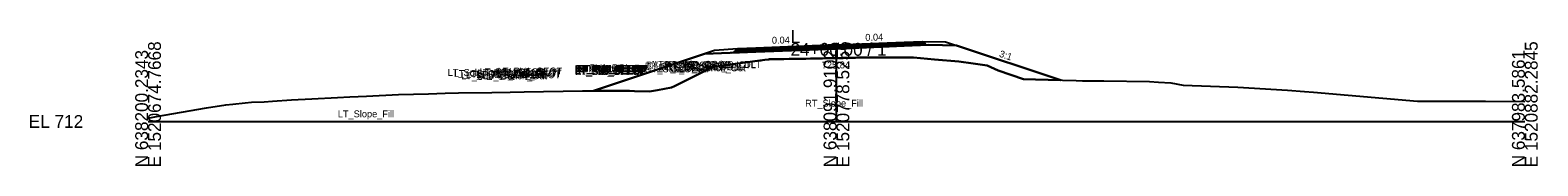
# Model space of a CAD drawing. Extents: x -26 to 3903, y -10 to 9531.
# Drawn here: x 974.3 to 1302.8, y 3990.3 to 4019.9 of the extents above; entities that cross this region are included whole.
import ezdxf

# ---------------------------------------------------------------- set-up
doc = ezdxf.new("R2010")
doc.units = 0
for name, color, linetype in [('Default', 7, 'Continuous'), ('Exist Cross Section Cell', 7, 'Continuous'), ('Exist XS Center Line Elevation Label', 7, 'Continuous'), ('Exist XS Ground Line', 7, 'Continuous'), ('Prop CMT Conc Surface', 7, 'Continuous'), ('Prop CMT Pvmt Course 1', 7, 'Continuous'), ('Prop CMT Pvmt Course 2', 7, 'Continuous'), ('Prop CMT Pvmt Course 3', 7, 'Continuous'), ('Prop CMT Pvmt Surface', 7, 'Continuous'), ('Prop CMT Pvmt Surface Shoulder', 7, 'Continuous'), ('Prop CMT Shld Paved Course 1', 7, 'Continuous'), ('Prop CMT Shld Paved Course 2', 7, 'Continuous'), ('Prop CMT Shld Paved Course 3', 7, 'Continuous'), ('Prop CMT Slope Grass', 7, 'Continuous'), ('Prop CMT Subgrade Earthwork', 7, 'Continuous'), ('Prop XS Earthwork Shape', 7, 'Continuous'), ('Prop XS SE Text', 7, 'Continuous'), ('Prop XS Side Slope Text', 7, 'Continuous')]:
    doc.layers.add(name, color=color, linetype=linetype)

msp = doc.modelspace()

# ---------------------------------------------------------------- linework, layer by layer
at = {"layer": 'Exist Cross Section Cell'}
for p, q in [((1150, 4000), (1150, 4017.14)), ((1000, 4000), (1150, 4000)), ((1150, 4000), (1300, 4000))]:
    msp.add_line(p, q, dxfattribs=at)
at = {"layer": 'Exist XS Ground Line'}
msp.add_lwpolyline([(1000, 4000.71), (1001.87, 4001.06), (1012.72, 4002.98), (1016.94, 4003.62), (1018.49, 4003.79), (1021.17, 4004.04), (1022.57, 4004.18), (1025.3, 4004.32), (1027.1, 4004.46), (1031.28, 4004.75), (1035.65, 4004.93), (1041.25, 4005.2), (1043.99, 4005.38), (1047.58, 4005.5), (1054.57, 4005.86), (1061.09, 4006.03), (1064.71, 4006.18), (1067.62, 4006.24), (1074.94, 4006.31), (1078.92, 4006.39), (1081.98, 4006.48), (1094.64, 4006.67), (1095.14, 4006.67), (1095.79, 4006.67), (1097.45, 4006.67), (1104.89, 4006.67), (1105.99, 4006.63), (1109.27, 4006.55), (1111.03, 4006.83), (1114.04, 4007.38), (1114.68, 4007.71), (1120.53, 4010.62), (1121.55, 4011.11), (1122.79, 4011.84), (1124.76, 4012.16), (1134.42, 4013.45), (1135.21, 4013.56), (1135.27, 4013.56), (1135.4, 4013.57), (1136.27, 4013.59), (1136.63, 4013.59), (1137.45, 4013.61), (1138.57, 4013.62), (1139.72, 4013.64), (1140.33, 4013.65), (1140.93, 4013.66), (1142.12, 4013.68), (1143.35, 4013.7), (1144.37, 4013.72), (1146.94, 4013.78), (1147.4, 4013.79), (1147.83, 4013.8), (1149.3, 4013.83), (1150.07, 4013.85), (1150.15, 4013.85), (1150.44, 4013.85), (1151.3, 4013.87), (1154.17, 4013.92), (1154.46, 4013.93), (1154.74, 4013.93), (1157.77, 4013.98), (1157.99, 4013.99), (1158.2, 4013.99), (1161.38, 4013.99), (1161.66, 4013.99), (1161.83, 4013.99), (1163.85, 4013.99), (1165, 4013.98), (1165.13, 4013.97), (1166.5, 4013.97), (1166.76, 4013.97), (1171.38, 4013.55), (1176.7, 4013.07), (1179.81, 4012.64), (1182.82, 4012.2), (1185.23, 4011.15), (1190.77, 4009.2), (1193.38, 4009.14), (1202.25, 4008.91), (1203.65, 4008.89), (1208.28, 4008.84), (1218.23, 4008.69), (1220.17, 4008.56), (1222.87, 4008.43), (1225.57, 4007.95), (1237.45, 4007.5), (1248.31, 4006.8), (1251.97, 4006.52), (1253.94, 4006.41), (1276.59, 4004.43), (1282.17, 4004.45), (1291.43, 4004.45), (1300, 4004.38)], dxfattribs=at)
at = {"layer": 'Prop CMT Pvmt Course 1'}
for points in [[(1149.97, 4016.73), (1132.41, 4016.02)], [(1132.41, 4015.77), (1149.97, 4016.48)], [(1132.41, 4016.02), (1132.41, 4015.77)], [(1149.97, 4016.73), (1164.76, 4017.32)], [(1164.76, 4017.07), (1149.97, 4016.48)], [(1149.97, 4016.48), (1149.97, 4016.73)], [(1149.97, 4016.48), (1149.97, 4016.73)], [(1164.76, 4017.32), (1164.76, 4017.07)]]:
    msp.add_lwpolyline(points, dxfattribs=at)
msp.add_lwpolyline([(1149.97, 4016.48), (1149.97, 4016.6), (1149.97, 4016.6), (1149.97, 4016.48)], close=True, dxfattribs=at)
msp.add_lwpolyline([(1149.97, 4016.48), (1149.97, 4016.6), (1149.97, 4016.6), (1149.97, 4016.48)], close=True, dxfattribs=at)
at = {"layer": 'Prop CMT Pvmt Course 2'}
for points in [[(1149.97, 4016.48), (1132.41, 4015.77)], [(1132.41, 4015.44), (1149.97, 4016.14)], [(1132.41, 4015.77), (1132.41, 4015.44)], [(1149.97, 4016.48), (1164.76, 4017.07)], [(1164.76, 4016.73), (1149.97, 4016.14)], [(1149.97, 4016.14), (1149.97, 4016.48)], [(1149.97, 4016.14), (1149.97, 4016.48)], [(1164.76, 4017.07), (1164.76, 4016.73)]]:
    msp.add_lwpolyline(points, dxfattribs=at)
at = {"layer": 'Prop CMT Pvmt Course 3'}
for points in [[(1149.97, 4016.14), (1132.41, 4015.44)], [(1132.41, 4015.19), (1149.97, 4015.89)], [(1132.41, 4015.44), (1132.41, 4015.19)], [(1149.97, 4016.14), (1164.76, 4016.73)], [(1164.76, 4016.48), (1149.97, 4015.89)], [(1149.97, 4015.89), (1149.97, 4016.14)], [(1149.97, 4015.89), (1149.97, 4016.14)], [(1164.76, 4016.73), (1164.76, 4016.48)]]:
    msp.add_lwpolyline(points, dxfattribs=at)
at = {"layer": 'Prop CMT Pvmt Surface'}
for points in [[(1149.97, 4016.73), (1132.41, 4016.02)], [(1149.97, 4016.73), (1164.76, 4017.32)]]:
    msp.add_lwpolyline(points, dxfattribs=at)
at = {"layer": 'Prop CMT Pvmt Surface Shoulder'}
for points in [[(1132.41, 4016.02), (1128.41, 4015.86)], [(1164.76, 4017.32), (1168.76, 4017.48)]]:
    msp.add_lwpolyline(points, dxfattribs=at)
at = {"layer": 'Prop CMT Shld Paved Course 1'}
for points in [[(1132.41, 4016.02), (1128.41, 4015.86), (1128.15, 4015.6)], [(1128.15, 4015.6), (1132.41, 4015.77)], [(1132.41, 4015.77), (1132.41, 4016.02)], [(1164.76, 4017.32), (1168.76, 4017.48), (1169, 4017.24)], [(1164.76, 4017.07), (1164.76, 4017.32)], [(1169, 4017.24), (1164.76, 4017.07)]]:
    msp.add_lwpolyline(points, dxfattribs=at)
at = {"layer": 'Prop CMT Shld Paved Course 2'}
for points in [[(1132.41, 4015.77), (1128.15, 4015.6), (1127.8, 4015.26)], [(1127.8, 4015.26), (1132.41, 4015.44)], [(1132.41, 4015.44), (1132.41, 4015.77)], [(1164.76, 4017.07), (1169, 4017.24), (1169.32, 4016.92)], [(1164.76, 4016.73), (1164.76, 4017.07)], [(1169.32, 4016.92), (1164.76, 4016.73)]]:
    msp.add_lwpolyline(points, dxfattribs=at)
at = {"layer": 'Prop CMT Shld Paved Course 3'}
for p, q in [((1127.8, 4015.26), (1127.54, 4014.99)), ((1169.32, 4016.92), (1169.56, 4016.68))]:
    msp.add_line(p, q, dxfattribs=at)
for points in [[(1127.04, 4014.97), (1132.41, 4015.19)], [(1132.41, 4015.44), (1127.8, 4015.26), (1127.54, 4014.99)], [(1132.41, 4015.19), (1132.41, 4015.44)], [(1164.76, 4016.73), (1169.32, 4016.92), (1169.56, 4016.68)], [(1164.76, 4016.48), (1164.76, 4016.73)], [(1170.06, 4016.7), (1164.76, 4016.48)]]:
    msp.add_lwpolyline(points, dxfattribs=at)
at = {"layer": 'Prop CMT Slope Grass'}
for points in [[(1128.41, 4015.86), (1123.41, 4015.46), (1097.03, 4006.67)], [(1168.76, 4017.48), (1173.76, 4017.38), (1198.9, 4009)]]:
    msp.add_lwpolyline(points, dxfattribs=at)
at = {"layer": 'Prop CMT Subgrade Earthwork'}
for points in [[(1132.41, 4015.19), (1121.25, 4014.74)], [(1149.97, 4015.89), (1132.41, 4015.19)], [(1149.97, 4015.89), (1164.76, 4016.48)], [(1164.76, 4016.48), (1170.06, 4016.7)], [(1170.06, 4016.7), (1176.17, 4016.57)]]:
    msp.add_lwpolyline(points, dxfattribs=at)
at = {"layer": 'Prop XS Earthwork Shape'}
for points in [[(1161.83, 4013.99), (1163.85, 4013.99), (1165, 4013.98), (1165.13, 4013.97), (1166.5, 4013.97), (1166.76, 4013.97), (1171.38, 4013.55), (1176.7, 4013.07), (1179.81, 4012.64), (1182.82, 4012.2), (1185.23, 4011.15), (1190.77, 4009.2), (1193.38, 4009.14), (1198.9, 4009), (1176.17, 4016.57), (1170.06, 4016.7), (1164.76, 4016.48), (1149.97, 4015.89), (1132.41, 4015.19), (1121.25, 4014.74), (1097.03, 4006.67), (1097.45, 4006.67), (1104.89, 4006.67), (1105.99, 4006.63), (1109.27, 4006.55), (1111.03, 4006.83), (1114.04, 4007.38), (1114.68, 4007.71), (1120.53, 4010.62), (1121.55, 4011.11), (1122.79, 4011.84), (1124.76, 4012.16), (1134.42, 4013.45), (1135.21, 4013.56), (1135.4, 4013.57), (1136.27, 4013.59), (1136.63, 4013.59), (1137.45, 4013.61), (1138.57, 4013.62), (1139.72, 4013.64), (1140.33, 4013.65), (1140.93, 4013.66), (1142.12, 4013.68), (1143.35, 4013.7), (1144.37, 4013.72), (1146.94, 4013.78), (1147.4, 4013.79), (1147.83, 4013.8), (1149.3, 4013.83), (1150.07, 4013.85), (1150.44, 4013.85), (1151.3, 4013.87), (1154.17, 4013.92), (1154.46, 4013.93), (1154.74, 4013.93), (1157.77, 4013.98), (1157.99, 4013.99), (1158.2, 4013.99), (1161.38, 4013.99), (1161.66, 4013.99)], [(1170.06, 4016.7), (1176.17, 4016.57), (1198.9, 4009), (1193.38, 4009.14), (1190.77, 4009.2), (1185.23, 4011.15), (1182.82, 4012.2), (1179.81, 4012.64), (1176.7, 4013.07), (1171.38, 4013.55), (1166.76, 4013.97), (1166.5, 4013.97), (1165.13, 4013.97), (1165, 4013.98), (1163.85, 4013.99), (1161.83, 4013.99), (1161.66, 4013.99), (1161.38, 4013.99), (1158.2, 4013.99), (1157.99, 4013.99), (1157.77, 4013.98), (1154.74, 4013.93), (1154.46, 4013.93), (1154.17, 4013.92), (1151.3, 4013.87), (1150.44, 4013.85), (1150.07, 4013.85), (1149.3, 4013.83), (1147.83, 4013.8), (1147.4, 4013.79), (1146.94, 4013.78), (1144.37, 4013.72), (1143.35, 4013.7), (1142.12, 4013.68), (1140.93, 4013.66), (1140.33, 4013.65), (1139.72, 4013.64), (1138.57, 4013.62), (1137.45, 4013.61), (1136.63, 4013.59), (1136.27, 4013.59), (1135.4, 4013.57), (1135.21, 4013.56), (1134.42, 4013.45), (1124.76, 4012.16), (1122.79, 4011.84), (1121.55, 4011.11), (1120.53, 4010.62), (1114.68, 4007.71), (1114.04, 4007.38), (1111.03, 4006.83), (1109.27, 4006.55), (1105.99, 4006.63), (1104.89, 4006.67), (1097.45, 4006.67), (1097.03, 4006.67), (1121.25, 4014.74), (1132.41, 4015.19), (1149.97, 4015.89), (1164.76, 4016.48)]]:
    msp.add_lwpolyline(points, close=True, dxfattribs=at)

# ---------------------------------------------------------------- texts
at = {"layer": 'Default'}
msp.add_text('-', height=0.0001, dxfattribs=at).set_placement((1000, 4000))
at = {"layer": 'Exist Cross Section Cell'}
for s, p in [('L', (1140, 4017.14)), ('24+00.00 / 1', (1140, 4014.34)), ('EL 712', (974, 3998.6))]:
    msp.add_text(s, height=2.8, dxfattribs=at).set_placement(p)
for s, p in [('N 638200.2343', (1000, 3990)), ('E 1520674.7668', (1002.8, 3990)), ('N 638091.9102', (1150, 3990)), ('E 1520778.5256', (1152.8, 3990)), ('N 637983.5861', (1300, 3990)), ('E 1520882.2845', (1302.8, 3990))]:
    msp.add_text(s, height=2.8, rotation=90, dxfattribs=at).set_placement(p)
at = {"layer": 'Exist XS Center Line Elevation Label'}
msp.add_text('725.84', height=1.5, rotation=0.8401, dxfattribs=at).set_placement((1146.83, 4011.52))
at = {"layer": 'Prop CMT Conc Surface'}
for s, p in [('LT_Sub_Trench_Out_DLT', (1065.3, 4009.95)), ('LT_PS1_OEOP', (1072.27, 4010.11)), ('LT_PV2_OEOT', (1076.03, 4010.02)), ('LT_PV1_OEOT', (1076.21, 4010.27)), ('RT_PV2_OEEOP', (1092.97, 4010.73)), ('RT_PV3_OEEOP', (1092.97, 4010.39)), ('RT_Sub_OEEOP', (1093.01, 4010.14)), ('LT_PV2_OEEOP', (1093.06, 4010.73)), ('LT_PV3_OEEOP', (1093.06, 4010.39)), ('LT_Sub_OEEOP', (1093.1, 4010.14)), ('RT_PV1_OEEOP', (1093.15, 4010.85)), ('LT_PV1_OEEOP', (1093.24, 4010.85)), ('RT_PV2_IEEOP', (1093.54, 4010.73)), ('LT_PV2_IEEOP', (1093.63, 4010.73)), ('RT_PV1_IEEOP', (1093.72, 4010.85)), ('LT_PV1_IEEOP', (1093.81, 4010.85)), ('PV2_PGL', (1096, 4010.73)), ('PV1_PGL', (1096.18, 4010.98)), ('RT_PV2_OEOT', (1108.29, 4011.32)), ('RT_PV3_OEOT', (1108.29, 4010.98)), ('RT_Sub_OEOT', (1108.33, 4010.73)), ('RT_PV1_OEOT', (1108.47, 4011.57)), ('RT_Sub_Trench_Out_DLT', (1109.69, 4011.69)), ('RT_Sub_Trench_Out', (1111.14, 4010.95)), ('RT_PS3_Shelf_Out', (1111.72, 4011.19)), ('RT_PS1_OEOP', (1112.53, 4011.73)), ('RT_PS2_OEOP', (1112.59, 4011.49)), ('RT_PS3_OEOP', (1112.91, 4011.17)), ('RT_GS_OS_CTL', (1116.87, 4011.63)), ('LT_GS_OS_CTL', (1066.61, 4009.71)), ('LT_Sub_Trench_Out', (1068.21, 4009.22)), ('LT_PS3_Shelf_Out', (1069.29, 4009.49)), ('LT_PS3_OEOP', (1071.48, 4009.51)), ('LT_PS2_OEOP', (1071.83, 4009.85)), ('LT_PV3_OEOT', (1076.03, 4009.69)), ('LT_Sub_OEOT', (1076.06, 4009.44)), ('RT_Slope_Fill', (1143.19, 4003.24)), ('LT_Slope_Fill', (1041.35, 4000.91))]:
    msp.add_text(s, height=1.5, dxfattribs=at).set_placement(p)
at = {"layer": 'Prop XS SE Text'}
for p in [(1135.95, 4016.97), (1156.3, 4017.6)]:
    msp.add_text('0.04', height=1.5, rotation=1.1458, dxfattribs=at).set_placement(p)
at = {"layer": 'Prop XS Side Slope Text'}
for rotation, p in [(341.5668, (1185.34, 4014.17)), (18.4332, (1108.68, 4011.06))]:
    msp.add_text('3:1', height=1.5, rotation=rotation, dxfattribs=at).set_placement(p)

doc.saveas('drawing.dxf')
